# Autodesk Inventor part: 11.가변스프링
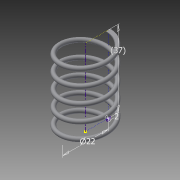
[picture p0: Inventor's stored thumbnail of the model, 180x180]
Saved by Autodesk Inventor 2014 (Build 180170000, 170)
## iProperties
Created: 2016-01
Part Number: 11.가변스프링
Material: Generic
Document SubType Name: Modeling
Designer: Administrator
Density: 1 g/cm^3
Appearance: Default
Author: Administrator
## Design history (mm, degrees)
sketch "스케치1"
  geometry: L1 (0, 37)-(11, 37); L2 (11, 37)-(11, 0); L3 (11, 0)-(0, 0); L4 (0, 0)-(0, 37); C1 r 1 at (11, 0); 1 further point
  constraints: 8 end point, 2 coincident, 2 parallel, 1 centre point, 1 horizontal, 1 perpendicular
  dimensions: "d0" = 2 diameter of C1; "d1" = 22 diameter of L2 L4; "d2" = 37 distance of L1.end L2.end (derived)
feature "코일1" pitch "d3" = 10; turns "d5" = 5; dims "d4" = 37 (= d2), "d6" = 0, angle "d7" = 90 deg, angle "d8" = 90 deg, "d9" = 0, "d10" = 0
sketch "스케치2"
  geometry: L1 (0, 12)-(0, 10) reference; 1 further point
  constraints: 1 vertical alignment
extrude "돌출1" cut sketch "스케치2" distance "d11" = 10; taper "d12" = 0 deg
node "작업 평면1"
sketch "스케치3"
  geometry: L1 (10, 0)-(12, 0) reference; 1 further point
  constraints: 1 horizontal alignment
extrude "돌출2" cut sketch "스케치3" distance "d14" = 10; taper "d15" = 0 deg
node "솔리드1"
node "절단 모서리 투영1"
node "절단 모서리 투영2"
other parameters: "d13" = 0
